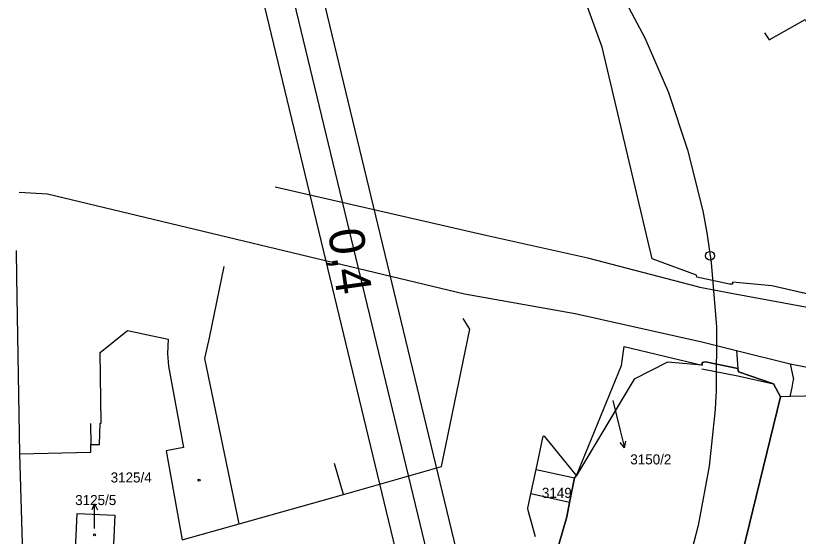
# Model space of a CAD drawing. Extents: x -738085 to -734306, y -1122197 to -1119753.
# Drawn here: x -734573.1 to -734440.5, y -1120130.5 to -1120042.4 of the extents above; entities that cross this region are included whole.
import ezdxf

# ---------------------------------------------------------------- set-up
doc = ezdxf.new("R2010")
doc.units = 0
for name, color, linetype in [('Hranice parcel', 7, 'Continuous'), ('Parcelní čísla', 7, 'Continuous'), ('Pop  PČ popisy', 7, 'Continuous'), ('SŽDC', 7, 'Continuous'), ('Vnitřní kresba', 7, 'Continuous'), ('Vrstva 1', 7, 'Continuous'), ('Vrstva 53', 7, 'Continuous'), ('Vrstva 7', 7, 'Continuous'), ('Značky budov', 7, 'Continuous')]:
    doc.layers.add(name, color=color, linetype=linetype)

msp = doc.modelspace()

# ---------------------------------------------------------------- linework, layer by layer
at = {"layer": 'Hranice parcel'}
for p, q in [((-734426.51, -1120092.35), (-734445.03, -1120088.16)), ((-734572.41, -1120116.59), (-734571.92, -1120133.6)), ((-734517.54, -1120123.46), (-734519.06, -1120118.19)), ((-734535.22, -1120128.39), (-734517.54, -1120123.46)), ((-734479.27, -1120124.78), (-734485.81, -1120123.35)), ((-734544.9, -1120131.12), (-734535.22, -1120128.39))]:
    msp.add_line(p, q, dxfattribs=at)
for points in [[(-734446.28, -1120045.36), (-734445.48, -1120046.51), (-734439.4, -1120043.1), (-734425.34, -1120067.55), (-734423.76, -1120081.88), (-734426.51, -1120092.35)], [(-734403.56, -1120099.44), (-734432.9, -1120092.95), (-734451.59, -1120089.48), (-734457.2, -1120088.44), (-734457.58, -1120088.34), (-734476.2, -1120083.49), (-734493.47, -1120079.65), (-734529.14, -1120071.48)], [(-734572.48, -1120072.28), (-734567.68, -1120072.61), (-734497.04, -1120089.52), (-734478.31, -1120092.85), (-734456.87, -1120097.64), (-734450.98, -1120099.09), (-734441.92, -1120101.33), (-734431.18, -1120103.41), (-734397.21, -1120110.97), (-734390.44, -1120112.99), (-734384.75, -1120115.04), (-734379.59, -1120118.25)], [(-734572.98, -1120082.2), (-734572.91, -1120086.61), (-734572.41, -1120116.59)], [(-734535.22, -1120128.39), (-734541.02, -1120100.47), (-734540.24, -1120096.93), (-734537.79, -1120084.87)], [(-734517.54, -1120123.46), (-734500.97, -1120118.7), (-734496.16, -1120095.47), (-734497.3, -1120093.7)], [(-734572.41, -1120116.59), (-734560.34, -1120116.31), (-734560.35, -1120115), (-734558.85, -1120114.99), (-734558.79, -1120111.41), (-734558.59, -1120111.41), (-734558.74, -1120099.45), (-734554.13, -1120095.73), (-734547.23, -1120097.18), (-734547.39, -1120099.61), (-734547.17, -1120101.76), (-734544.66, -1120115.52), (-734547.56, -1120116.06), (-734544.9, -1120131.12)], [(-734478.1, -1120120.24), (-734470.47, -1120101.61), (-734470.01, -1120098.43)], [(-734456.81, -1120101.58), (-734462.68, -1120101.09), (-734468.35, -1120103.94), (-734478.1, -1120120.24)], [(-734443.58, -1120106.95), (-734444.72, -1120104.71), (-734450.69, -1120102.69), (-734450.79, -1120102.16), (-734456.26, -1120101.03), (-734456.8, -1120101.1), (-734456.81, -1120101.58)], [(-734443.58, -1120106.95), (-734449.99, -1120133.29), (-734459.08, -1120154.68), (-734484.08, -1120187.66), (-734500.69, -1120202.26), (-734522.92, -1120216.44), (-734543.71, -1120224.54), (-734562.36, -1120229.51), (-734589.59, -1120229.56), (-734612.32, -1120225.54), (-734626.24, -1120221.38), (-734644.28, -1120218.16), (-734681.74, -1120210.16)], [(-734434.38, -1120106.7), (-734441.91, -1120106.9), (-734443.58, -1120106.95)], [(-734485.81, -1120123.35), (-734484.93, -1120119.2), (-734483.75, -1120113.58)], [(-734478.1, -1120120.24), (-734483.49, -1120113.64), (-734483.75, -1120113.58)], [(-734479.27, -1120124.78), (-734478.43, -1120120.64), (-734478.1, -1120120.24)], [(-734485.02, -1120130.59), (-734486.3, -1120126.17), (-734486.35, -1120125.79), (-734485.81, -1120123.35)], [(-734485.26, -1120173.47), (-734483.91, -1120171.99), (-734473.68, -1120156.85), (-734466.2, -1120141.71), (-734474.93, -1120139.44), (-734481.07, -1120131.93), (-734479.71, -1120127.23), (-734479.27, -1120124.78)], [(-734562.98, -1120134.02), (-734562.66, -1120126.69), (-734556.3, -1120126.92), (-734556.63, -1120134.32)]]:
    msp.add_lwpolyline(points, dxfattribs=at)
at = {"layer": 'Pop  PČ popisy'}
for p, q in [((-734471.96, -1120107.57), (-734470.71, -1120112.62)), ((-734470.71, -1120112.62), (-734469.98, -1120115.53)), ((-734469.98, -1120115.53), (-734470.71, -1120114.68)), ((-734469.98, -1120115.53), (-734469.74, -1120114.44)), ((-734559.7, -1120125.03), (-734560.2, -1120126.03)), ((-734559.7, -1120128.03), (-734559.7, -1120125.03)), ((-734559.7, -1120125.03), (-734559.2, -1120126.03)), ((-734559.7, -1120129.18), (-734559.7, -1120128.03))]:
    msp.add_line(p, q, dxfattribs=at)
at = {"layer": 'SŽDC'}
for p, q in [((-734462.68, -1120101.09), (-734468.35, -1120103.94)), ((-734456.81, -1120101.58), (-734462.68, -1120101.09)), ((-734456.8, -1120101.1), (-734456.81, -1120101.58)), ((-734456.26, -1120101.03), (-734456.8, -1120101.1)), ((-734450.79, -1120102.16), (-734456.26, -1120101.03)), ((-734450.69, -1120102.69), (-734450.79, -1120102.16)), ((-734444.72, -1120104.71), (-734450.69, -1120102.69)), ((-734443.58, -1120106.95), (-734444.72, -1120104.71)), ((-734449.99, -1120133.29), (-734443.58, -1120106.95)), ((-734478.43, -1120120.64), (-734479.27, -1120124.78)), ((-734478.1, -1120120.24), (-734478.43, -1120120.64)), ((-734479.27, -1120124.78), (-734479.71, -1120127.23)), ((-734479.71, -1120127.23), (-734481.07, -1120131.93))]:
    msp.add_line(p, q, dxfattribs=at)
msp.add_lwpolyline([(-734468.35, -1120103.94), (-734471.54, -1120109.27), (-734478.1, -1120120.24)], dxfattribs=at)
at = {"layer": 'Vnitřní kresba'}
for p, q in [((-734450.98, -1120099.09), (-734450.79, -1120102.16)), ((-734456.89, -1120102.17), (-734450.79, -1120103.35)), ((-734441.92, -1120101.33), (-734441.33, -1120103.98)), ((-734450.79, -1120103.35), (-734444.72, -1120104.71)), ((-734441.6, -1120105.35), (-734441.33, -1120103.98)), ((-734441.91, -1120106.9), (-734441.6, -1120105.35)), ((-734560.38, -1120111.43), (-734560.35, -1120115)), ((-734484.93, -1120119.2), (-734478.43, -1120120.64))]:
    msp.add_line(p, q, dxfattribs=at)
at = {"layer": 'Vrstva 1'}
for points in [[(-734534.27, -1119984.39), (-735554.91, -1120230.88), (-735485.2, -1120519.57), (-734464.55, -1120273.08)], [(-734470.58, -1120269.4), (-735481.51, -1120513.53), (-735548.88, -1120234.56), (-734537.95, -1119990.43)], [(-734541.63, -1119996.45), (-735348.44, -1120191.3), (-735283.42, -1120460.56), (-734476.61, -1120265.71)]]:
    msp.add_lwpolyline(points, close=True, dxfattribs=at)
msp.add_lwpolyline([(-734472.03, -1120035.88), (-734466.54, -1120046.18), (-734462.52, -1120055.45), (-734459.28, -1120065.13), (-734456.73, -1120075.49), (-734456.03, -1120079.17), (-734455.32, -1120084.21), (-734454.4, -1120095.11), (-734454.44, -1120105.99), (-734454.54, -1120107.84), (-734454.6, -1120109.09), (-734455.62, -1120118.65), (-734457.52, -1120128.68), (-734458.98, -1120134.34)], dxfattribs=at)
at = {"layer": 'Vrstva 53'}
for points in [[(-734420.23, -1120093.77), (-734445.03, -1120088.16), (-734451.69, -1120087.53), (-734451.69, -1120087.85), (-734452.2, -1120087.89), (-734457.71, -1120086.67), (-734457.76, -1120086.33), (-734465.26, -1120083.59), (-734473.76, -1120047.8), (-734479.48, -1120032.06)], [(-734481.07, -1120131.93), (-734479.71, -1120127.23), (-734479.27, -1120124.78), (-734478.43, -1120120.64), (-734478.1, -1120120.24), (-734470.47, -1120101.61), (-734470.01, -1120098.43), (-734456.81, -1120101.58), (-734456.8, -1120101.1), (-734456.26, -1120101.03), (-734450.79, -1120102.16), (-734450.69, -1120102.69), (-734444.72, -1120104.71), (-734443.58, -1120106.95), (-734449.97, -1120133.28)]]:
    msp.add_lwpolyline(points, dxfattribs=at)
at = {"layer": 'Vrstva 7'}
msp.add_circle((-734455.48, -1120083.07), 0.75, dxfattribs=at)
at = {"layer": 'Značky budov'}
for centre in [(-734542.02, -1120121.04), (-734559.71, -1120130.29)]:
    msp.add_circle(centre, 0.175, dxfattribs=at)

# ---------------------------------------------------------------- texts
at = {"layer": 'Parcelní čísla'}
for s, p in [('3150/2', (-734468.99, -1120118.36)), ('3125/4', (-734556.99, -1120121.42)), ('3149', (-734483.96, -1120124.02)), ('3125/5', (-734562.99, -1120125.24))]:
    msp.add_text(s, height=1.7, dxfattribs=at).set_placement(p)
at = {"layer": 'Vrstva 7'}
msp.add_text('0,4', height=6, rotation=278.0059, dxfattribs=at).set_placement((-734520.2, -1120078.82))

doc.saveas('drawing.dxf')
